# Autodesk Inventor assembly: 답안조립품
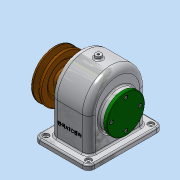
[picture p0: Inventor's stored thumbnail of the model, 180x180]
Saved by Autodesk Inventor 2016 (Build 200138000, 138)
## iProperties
Created: 2018-08
Part Number: 답안조립품
Material: 일반
Document SubType Name: Assembly
Designer: Administrator
Author: Administrator
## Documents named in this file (14)
- C:\Users\Administrator\Desktop\480811V1002\답안조립품.iam
- C:\Users\Administrator\Desktop\480811V1002\본체.ipt
- C:\Users\Administrator\Desktop\480811V1002\뒤커버.ipt
- C:\Users\Administrator\Desktop\480811V1002\볼트 M4.ipt
- C:\Users\Administrator\Desktop\480811V1002\축.ipt
- C:\Users\Administrator\Desktop\480811V1002\키 6x6x22.ipt
- C:\Users\Administrator\Desktop\480811V1002\베어링 6203.ipt
- C:\Users\Administrator\Desktop\480811V1002\스퍼기어.ipt
- C:\Users\Administrator\Desktop\480811V1002\부시.ipt
- C:\Users\Administrator\Desktop\480811V1002\앞커버.ipt
- C:\Users\Administrator\Desktop\480811V1002\오일 실 28 40 8.ipt
- C:\Users\Administrator\Desktop\480811V1002\키 5x5x18.ipt
- C:\Users\Administrator\Desktop\480811V1002\V-벨트풀리.ipt
- C:\Users\Administrator\Desktop\480811V1002\멈춤나사 M4.ipt
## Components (1 placed, 1 different names)
1. V-벨트풀리:1
